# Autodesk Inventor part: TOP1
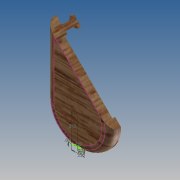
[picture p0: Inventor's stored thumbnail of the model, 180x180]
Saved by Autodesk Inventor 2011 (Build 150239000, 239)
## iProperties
Created: 2011-01
Part Number: TOP1
Document SubType Name: Modeling
Designer: Microsoft
Density: 1 g/cm^3
Author: Microsoft
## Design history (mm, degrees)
sketch "Sketch1"
  geometry: L1 (9.525, 0)-(9.525, 19.05); L2 (-9.525, 19.05)-(-9.525, 0); L3 (-9.525, 19.05)-(9.525, 0); A1 r 9.525 centre (0, 0) between (-9.525, 0) and (9.525, 0); A2 r 9.525 centre (0, 19.05) between (9.525, 19.05) and (-9.525, 19.05); 1 further point
  constraints: 6 end point, 4 point on circle, 3 tangent, 2 centre point, 1 coincident, 1 vertical alignment
  dimensions: "d3" = 9.525 radius of A2; "d4" = 9.525 radius of A1; "d5" = 19.05 distance of L1.start L1.end; "d6" = 19.05 distance of point (0, 0) A2.centre
extrude "Extrusion1" new body sketch "Sketch1" distance "d7" = 19.05; taper "d8" = 0 deg
workplane "Work Plane1"
sketch "Sketch7"
  geometry: L1 (-9.525, 19.05)-(9.525, 0) reference; L2 (-9.525, 0)-(-9.525, 19.05) reference; A1 r 9.525 centre (0, 0) between (-9.525, 0) and (9.525, 0) reference
extrude "Extrusion6" sketch "Sketch7" distance "d28" = 3.175; taper "d29" = 0 deg
fillet "Fillet1" dims "d37" = 2.54
sketch "Sketch11"
  geometry: L1 (9.525, 19.05)-(-9.525, 0); L2 (9.525, 19.05)-(5.951, 22.624); L3 (9.525, 19.05)-(-9.525, 0); L4 (7.841, 17.366)-(6.719, 16.244); A1 r 0.794 centre (7.28, 16.805) between (6.719, 16.244) and (7.841, 17.366)
  constraints: 8 end point, 3 point on line, 2 point on circle, 1 centre point, 1 collinear, 1 perpendicular
  dimensions: "d42" = 1.5875 diameter of A1; "d43" = 3.175 distance from line of L2 A1.centre
extrude "Extrusion10" join sketch "Sketch11" distance "d44" = 3.175; taper "d45" = 0 deg
sketch "Sketch12"
  geometry: L1 (7.28, 16.805)-(6.157, 15.682); L2 (6.719, 16.244)-(-9.525, 0) reference; L3 (7.28, 16.805)-(8.402, 17.927); L4 (9.525, 19.05)-(7.841, 17.366) reference; A1 r 0.794 centre (7.28, 16.805) between (6.719, 16.244) and (7.841, 17.366) reference; A2 r 1.587 centre (7.28, 16.805) between (6.157, 15.682) and (8.402, 17.927); 1 further point
  constraints: 4 end point, 2 point on circle, 2 point on line, 1 centre point, 1 coincident
  dimensions: "d46" = 3.175 diameter of A2
extrude "Extrusion11" join sketch "Sketch12" distance "d47" = 0.79375; taper "d48" = 0 deg
sketch "Sketch13"
  geometry: L1 (6.719, 16.244)-(-9.525, 0) reference; L2 (6.985, 0)-(9.525, 0) reference; L3 (7.938, 0)-(7.937, 15.36); A1 r 9.525 centre (0, 0) between (-9.525, 0) and (9.525, 0) reference; A2 r 7.938 centre (0, 0) between (-7.732, 1.793) and (7.938, 0); A3 r 1.587 centre (7.28, 16.805) between (6.157, 15.682) and (8.402, 17.927) reference
  constraints: 3 point on circle, 2 end point, 2 point on line, 1 centre point, 1 coincident, 1 perpendicular, 1 tangent
  dimensions: "d49" = 15.875 diameter of A2
extrude "Extrusion12" cut sketch "Sketch13" distance "d50" = 0.79375; taper "d51" = 0 deg
body "Solid1"
other parameters: "d17" = -6.35
